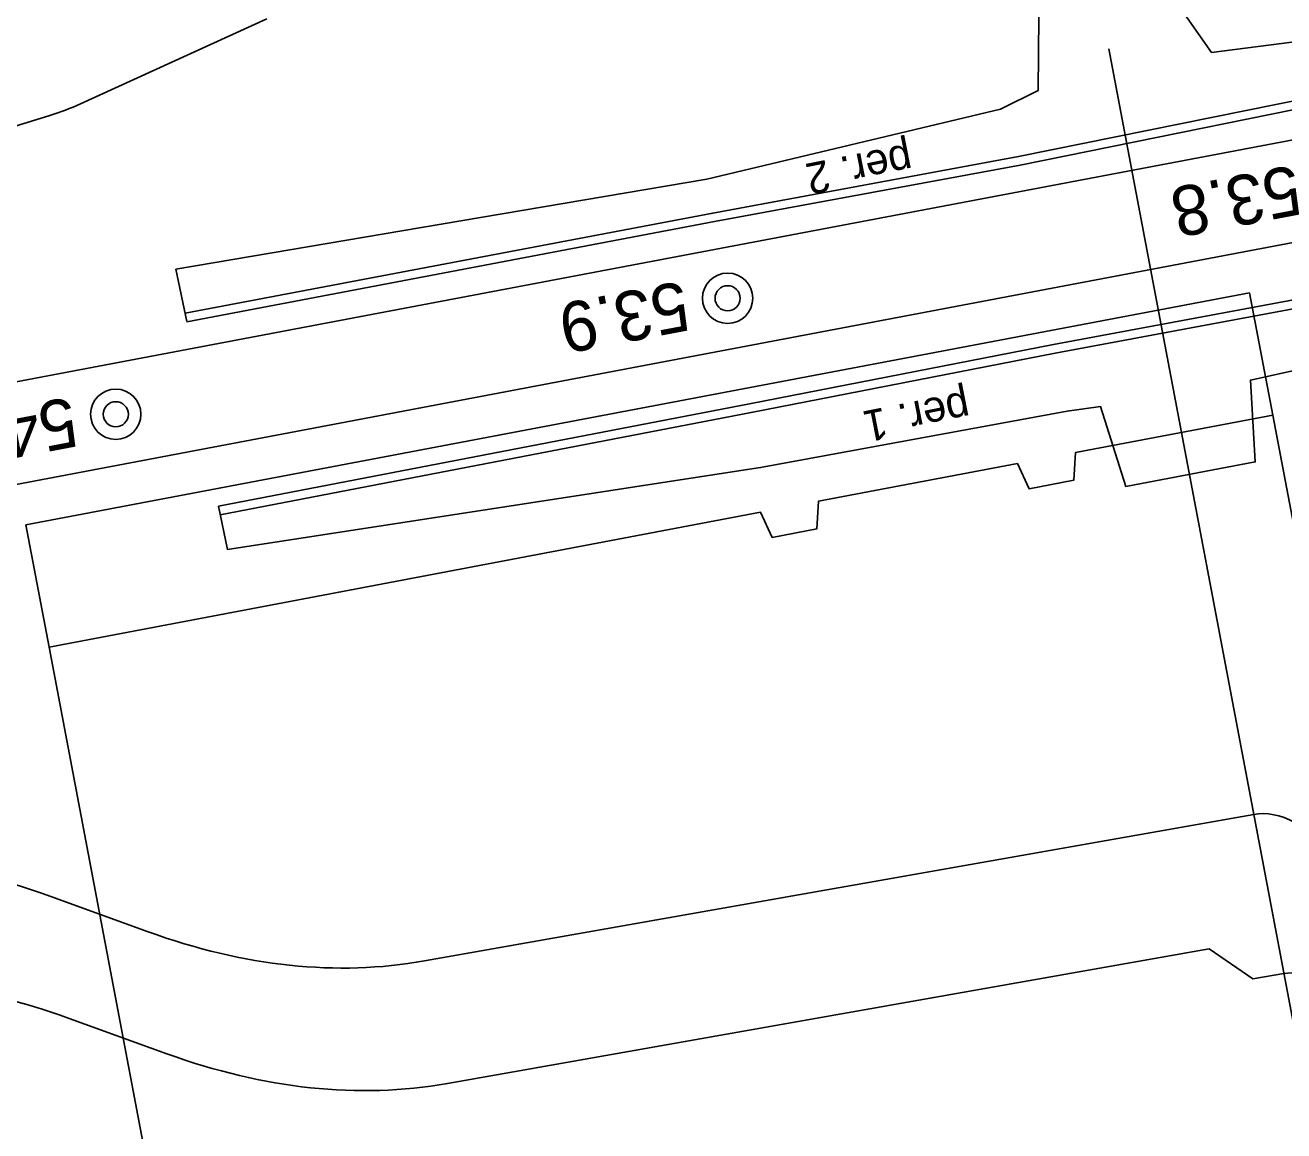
# Model space of a CAD drawing. Extents: x 6541740 to 6566395, y 5525066 to 5530361.
# Drawn here: x 6559039.2 to 6559089.8, y 5526484.5 to 5526528.9 of the extents above; entities that cross this region are included whole.
import ezdxf

# ---------------------------------------------------------------- set-up
doc = ezdxf.new("R2010")
doc.units = 0
for name, color, linetype in [('Domyślna', 7, 'Continuous'), ('ps_wymiarowanie', 7, 'Continuous'), ('TOR_PRZEK_P-komponent', 7, 'Continuous'), ('TOR_PRZEK_P-pomoc', 7, 'Continuous'), ('TOR_PS_OPIS_T-opis geometrii-wzdluz_plan zbior', 7, 'Continuous'), ('TOR_PS_OPIS_T-symbole geometrii', 7, 'Continuous'), ('TOR_PS_OPIS_T-szerokosc miedzytorzy', 7, 'Continuous'), ('TOR_PS_T-umocnienia skarp', 7, 'Continuous'), ('TOR_PS_T-wypelnienia', 7, 'Continuous'), ('TOR_RAMKI-ramka+tabelka 1', 7, 'Continuous')]:
    doc.layers.add(name, color=color, linetype=linetype)

# ---------------------------------------------------------------- blocks, each defined once
blk = doc.blocks.new('4010_1')
at = {"layer": 'Domyślna'}
for radius in [0.75, 0.375]:
    blk.add_circle((0, 0), radius, dxfattribs=at)
blk = doc.blocks.new('X KM right')
at = {"layer": 'Domyślna'}
blk.add_line((0, 0), (-16, 0), dxfattribs=at)

msp = doc.modelspace()

# ---------------------------------------------------------------- linework, layer by layer
at = {"layer": 'ps_wymiarowanie'}
msp.add_arc((6559037.297, 5526534.812), 10, 286.9951, 294.5218, dxfattribs=at)
msp.add_arc((6559037.297, 5526534.812), 10, 286.9951, 294.5218, dxfattribs=at)
at = {"layer": 'TOR_PRZEK_P-komponent'}
for p, q in [((6559263.549, 5526557.147), (6557908.193, 5526300.236)), ((6559264.303, 5526553.168), (6558036.172, 5526320.373))]:
    msp.add_line(p, q, dxfattribs=at)
at = {"layer": 'TOR_PRZEK_P-pomoc'}
for p, q in [((6559088.38, 5526518.132), (6559039.255, 5526508.82)), ((6559088.38, 5526518.132), (6559039.255, 5526508.82)), ((6559089.311, 5526513.219), (6559088.38, 5526518.132)), ((6559089.311, 5526513.219), (6559088.38, 5526518.132)), ((6559040.186, 5526503.907), (6559039.255, 5526508.82)), ((6559040.186, 5526503.907), (6559039.255, 5526508.82))]:
    msp.add_line(p, q, dxfattribs=at)
msp.add_lwpolyline([(6559089.311, 5526513.219), (6559081.386, 5526511.717), (6559081.322, 5526510.606), (6559079.529, 5526510.266), (6559079.062, 5526511.277), (6559071.07, 5526509.761), (6559071.006, 5526508.65), (6559069.212, 5526508.31), (6559068.746, 5526509.321), (6559040.186, 5526503.907)], dxfattribs=at)
msp.add_lwpolyline([(6559089.311, 5526513.219), (6559081.386, 5526511.717), (6559081.322, 5526510.606), (6559079.529, 5526510.266), (6559079.062, 5526511.277), (6559071.07, 5526509.761), (6559071.006, 5526508.65), (6559069.212, 5526508.31), (6559068.746, 5526509.321), (6559040.186, 5526503.907)], dxfattribs=at)
at = {"layer": 'TOR_PS_OPIS_T-symbole geometrii'}
for p, q in [((6559088.549, 5526497.196), (6559055.255, 5526491.313)), ((6559088.549, 5526497.196), (6559055.255, 5526491.313)), ((6559044.168, 5526492.484), (6559040.255, 5526493.903)), ((6559044.168, 5526492.484), (6559040.255, 5526493.903)), ((6559086.76, 5526491.803), (6559056.183, 5526486.4)), ((6559086.76, 5526491.803), (6559056.183, 5526486.4)), ((6559086.76, 5526491.803), (6559088.515, 5526490.59)), ((6559086.76, 5526491.803), (6559088.515, 5526490.59)), ((6559089.754, 5526490.809), (6559088.515, 5526490.59)), ((6559089.754, 5526490.809), (6559088.515, 5526490.59)), ((6559044.909, 5526487.59), (6559040.996, 5526489.009)), ((6559044.909, 5526487.59), (6559040.996, 5526489.009))]:
    msp.add_line(p, q, dxfattribs=at)
for centre, major_axis, start_param, end_param in [((6559094.576, 5526465.26), (-6.053, 31.931), 5.894354, 6.280077), ((6559094.576, 5526465.26), (-6.053, 31.931), 5.894354, 6.280077), ((6559085.087, 5526197.842), (-56.337, 297.208), 6.136011, 6.280144), ((6559085.087, 5526197.842), (-56.337, 297.208), 6.136011, 6.280144), ((6559000.077, 5526783.65), (-55.405, 292.295), 2.994419, 3.138484), ((6559000.077, 5526783.65), (-55.405, 292.295), 2.994419, 3.138484), ((6559085.087, 5526197.842), (-55.405, 292.295), 6.136011, 6.280144), ((6559085.087, 5526197.842), (-55.405, 292.295), 6.136011, 6.280144), ((6559094.576, 5526465.26), (-4.842, 25.545), 5.894354, 6.280077), ((6559094.576, 5526465.26), (-4.842, 25.545), 5.894354, 6.280077), ((6559000.077, 5526783.65), (-56.337, 297.208), 2.994419, 3.138484), ((6559000.077, 5526783.65), (-56.337, 297.208), 2.994419, 3.138484)]:
    msp.add_ellipse(centre, major_axis=major_axis, ratio=0.25, start_param=start_param, end_param=end_param, dxfattribs=at)
at = {"layer": 'TOR_PS_OPIS_T-szerokosc miedzytorzy'}
msp.add_line((6559082.729, 5526527.926), (6559094.389, 5526466.317), dxfattribs=at)
at = {"layer": 'TOR_PS_T-umocnienia skarp'}
for points in [[(6559094.348, 5526528.731), (6559086.855, 5526527.775), (6559085.149, 5526530.214), (6559079.914, 5526529.222), (6559079.894, 5526526.255), (6559078.375, 5526525.505), (6559066.585, 5526522.69), (6559055.931, 5526520.881), (6559045.277, 5526519.073)], [(6559094.348, 5526528.731), (6559086.855, 5526527.775), (6559085.149, 5526530.214), (6559079.914, 5526529.222), (6559079.894, 5526526.255), (6559078.375, 5526525.505), (6559066.585, 5526522.69), (6559055.931, 5526520.881), (6559045.277, 5526519.073)], [(6559045.65, 5526517.313), (6559066.827, 5526521.33), (6559079.103, 5526523.596), (6559094.66, 5526526.748)], [(6559045.65, 5526517.313), (6559066.827, 5526521.33), (6559079.103, 5526523.596), (6559094.66, 5526526.748)], [(6559045.715, 5526516.969), (6559066.892, 5526520.986), (6559079.168, 5526523.252), (6559094.726, 5526526.404)], [(6559045.715, 5526516.969), (6559066.892, 5526520.986), (6559079.168, 5526523.252), (6559094.726, 5526526.404)], [(6559045.277, 5526519.073), (6559045.718, 5526516.971)], [(6559045.277, 5526519.073), (6559045.718, 5526516.971)], [(6559046.989, 5526509.562), (6559047.341, 5526507.83), (6559058.045, 5526509.473), (6559068.75, 5526511.116), (6559081.061, 5526513.382), (6559082.391, 5526513.568), (6559083.416, 5526510.361), (6559088.607, 5526511.345), (6559088.413, 5526514.627), (6559095.967, 5526516.296), (6559096.483, 5526516.402), (6559095.883, 5526518.91)], [(6559046.989, 5526509.562), (6559047.341, 5526507.83), (6559058.045, 5526509.473), (6559068.75, 5526511.116), (6559081.061, 5526513.382), (6559082.391, 5526513.568), (6559083.416, 5526510.361), (6559088.607, 5526511.345), (6559088.413, 5526514.627), (6559095.967, 5526516.296), (6559096.483, 5526516.402), (6559095.883, 5526518.91)], [(6559095.89, 5526518.915), (6559080.512, 5526516.054), (6559068.306, 5526513.674), (6559046.992, 5526509.56)], [(6559095.89, 5526518.915), (6559080.512, 5526516.054), (6559068.306, 5526513.674), (6559046.992, 5526509.56)], [(6559095.955, 5526518.571), (6559080.578, 5526515.71), (6559068.371, 5526513.331), (6559047.057, 5526509.216)], [(6559095.955, 5526518.571), (6559080.578, 5526515.71), (6559068.371, 5526513.331), (6559047.057, 5526509.216)]]:
    msp.add_lwpolyline(points, dxfattribs=at)
at = {"layer": 'TOR_PS_T-wypelnienia'}
for p, q in [((6559041.447, 5526525.714), (6559048.922, 5526529.123)), ((6559041.447, 5526525.714), (6559048.922, 5526529.123)), ((6559033.134, 5526523.083), (6559040.22, 5526525.248)), ((6559033.134, 5526523.083), (6559040.22, 5526525.248))]:
    msp.add_line(p, q, dxfattribs=at)

# ---------------------------------------------------------------- block references
at = {"layer": 'TOR_PS_OPIS_T-opis geometrii-wzdluz_plan zbior'}
for p, xscale, yscale, rotation in [((6559093.967, 5526488.657), 1.562500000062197, 1.5625000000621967, -79.26676140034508), ((6559044.842, 5526479.345), 1.5625000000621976, 1.5625000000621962, -79.26676139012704)]:
    msp.add_blockref('X KM right', p, dxfattribs=dict(at, xscale=xscale, yscale=yscale, rotation=rotation))
at = {"layer": 'TOR_RAMKI-ramka+tabelka 1', "xscale": 1.345963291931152, "yscale": 1.345963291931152}
for p in [(6559067.425, 5526517.911), (6559042.862, 5526513.255)]:
    msp.add_blockref('4010_1', p, dxfattribs=at)

# ---------------------------------------------------------------- texts
at = {"layer": 'TOR_PS_T-umocnienia skarp'}
for s, p in [('per. 2', (6559074.7, 5526524.118)), ('per. 2', (6559074.7, 5526524.118)), ('per. 1', (6559077.011, 5526514.185)), ('per. 1', (6559077.011, 5526514.185))]:
    msp.add_text(s, height=1.2566, rotation=191.1151, dxfattribs=at).set_placement(p)
at = {"layer": 'TOR_RAMKI-ramka+tabelka 1'}
for s, p in [('53.8', (6559090.214, 5526523.274)), ('53.9', (6559065.649, 5526518.618)), ('54.0', (6559041.086, 5526513.962))]:
    msp.add_text(s, height=2, rotation=190.7691, dxfattribs=at).set_placement(p)

doc.saveas('drawing.dxf')
